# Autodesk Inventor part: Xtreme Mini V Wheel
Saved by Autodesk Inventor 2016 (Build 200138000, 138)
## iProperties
Created: 2015-11
Part Number: Xtreme Mini V Wheel
Material: Generic
Document SubType Name: Modeling
Designer: John
Density: 1 g/cm^3
Appearance: Default
Author: John
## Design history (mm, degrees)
feature "SOLID1"
body "Solid1"
